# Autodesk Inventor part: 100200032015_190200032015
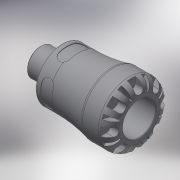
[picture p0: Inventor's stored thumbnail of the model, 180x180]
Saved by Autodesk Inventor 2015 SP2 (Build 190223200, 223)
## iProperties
Created: 2016-12
Part Number: 100200032015_190200032015
Material: Generic
Description: PLASSON MALE ADAPTOR 32X1.1/2" SERIES 1
Document SubType Name: Modeling
Designer: KIM
Mass: 447.839 g
Surface Area: 722.341 cm^2
Volume: 447.839 cm^3
Density: 1 g/cm^3
Appearance: Default
Author: KIM
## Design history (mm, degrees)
derived "1002.ipt"
feature "Solid1::1002.ipt"
tag "TaggingFeature1"
body "Solid1"
other parameters: "d0" = 86, "d1" = 23.1, "d2" = 32, "d4" = 58, "d6" = 55, "d8" = 49.3, "d13" = 7.2, "d14" = 7.2, "d15" = 0, "d17" = 360 deg, "d19" = 8 deg, "d20" = 0.64, "d21" = 0.64, "d22" = 8 deg, "d24" = 0, "d26" = 360 deg, "d32" = 0.925, "d33" = 5.8, "d34" = 47.803, "d35" = 2.66667, "d38" = 21, "d39" = 1.43409, "d42" = 11.2, "d43" = 7.36, "d45" = 14.112, "d46" = 0, "d59" = 360 deg, "d61" = 9.52, "d62" = 0.64, "d64" = 0, "d65" = 0.58, "d_" = 32, "E_" = 58, "H_" = 86, "l_" = 55, "R_" = 47.803, "l_2" = 21, "d9" = 9, "d11" = 58
